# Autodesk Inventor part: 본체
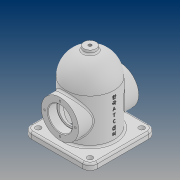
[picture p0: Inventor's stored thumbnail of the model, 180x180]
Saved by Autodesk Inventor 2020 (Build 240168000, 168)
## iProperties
Created: 2021-08
Part Number: 본체
Material: 일반
Document SubType Name: Modeling
Designer: PC312-
Density: 1 g/cm^3
Appearance: 기본값
Author: PC312-
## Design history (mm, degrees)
sketch "스케치1"
  geometry: C1 r 40 at (0, 0); 1 further point
  constraints: 1 centre point, 1 coincident
  dimensions: "d0" = 80 diameter of C1
extrude "돌출1" new body sketch "스케치1" distance "d1" = 36; taper "d3" = 0 deg; dims "d2" = 48, "d4" = 0
sketch "스케치2"
  geometry: C1 r 40 at (0, 0); 1 further point
  constraints: 1 centre point, 1 coincident
  dimensions: "d6" = 80 diameter of C1
extrude "돌출2" join sketch "스케치2" distance "d7" = 40; taper "d8" = 0 deg
fillet "모깎기2" dims "d9" = 40
sketch "스케치4"
  geometry: 1 further point
feature "쉘1" dims "d10" = 8
node "작업 평면1"
sketch "스케치5"
  geometry: L1 (-40, -48)-(40, -48) reference; C1 r 31 at (0, 0); 1 further point
  constraints: 1 centre point, 1 coincident
  dimensions: "d29" = 48 distance from line of L1 C1.centre; "d30" = 62 diameter of C1
extrude "돌출5" join sketch "스케치5" stored distance "d31" = 10; taper "d32" = 0 deg
sketch "스케치6"
  geometry: L1 (20, 50)-(20, 35); L2 (20, 35)-(16.5, 35); L3 (16.5, 35)-(16.5, -35); L4 (16.5, -35)-(20, -35); L5 (20, -35)-(20, -50); L6 (0, 71.621)-(0, -88.049); L7 (-48, -32)-(-48, 32) reference; L8 (20, 50)-(0, 50); L9 (20, -50)-(0, -50); L10 (31, 50)-(-31, 50) reference; L11 (31, -50)-(-31, -50) reference; 2 further points
  constraints: 16 end point, 4 horizontal, 4 point on line, 3 vertical, 2 collinear, 1 coincident
  dimensions: "d33" = 48 distance between parallel lines of L7 L6; "d34" = 15 distance between parallel lines of L2 L8; "d35" = 15 distance between parallel lines of L9 L4; "d36" = 40 diameter of L5 L6; "d37" = 33 diameter of L3 L6
revolve "회전3" sketch "스케치6" stored, may be unused: angle "d38" = 90 deg
sketch "스케치7"
  geometry: L1 (55, 55)-(-55, 55); L2 (-55, 55)-(-55, -55); L3 (-55, -55)-(55, -55); L4 (55, -55)-(55, 55); L5 (55, 55)-(-55, -55); L6 (-55, 55)-(55, -55); C1 r 32 at (0, 0) reference; 1 further point
  constraints: 12 end point, 2 midpoint, 2 parallel, 1 horizontal, 1 perpendicular
  dimensions: "d24" = 110 distance between parallel lines of L3 L1; "d25" = 110 distance between parallel lines of L2 L4
extrude "돌출4" join sketch "스케치7" distance "d26" = 10; taper "d27" = 0 deg
fillet "모깎기4" dims "d39" = 0.3
node "작업 평면2"
sketch "스케치8"
  geometry: C1 r 10 at (0, 0); 1 further point
  constraints: 1 centre point, 1 coincident
  dimensions: "d41" = 20 diameter of C1
extrude "돌출6" join sketch "스케치8" stored distance "d42" = 10; taper "d43" = 0 deg
sketch "스케치9"
  geometry: C1 r 10 at (0, 0) reference; 2 further points
  constraints: 1 coincident
hole "구멍1" sketch "스케치9" at (0, 0) diameter "d44" = 5.1881; stored, may be unused: countersink angle "d48" = 90 deg, drill point angle "d50" = 118 deg; dims "d45" = 18, "d46" = 4, "d47" = 2, "d49" = 16
sketch "스케치10"
  geometry: 2 further points
  constraints: 1 vertical alignment
  dimensions: "d51" = 25.5 distance of point (0, 0) point (0, 25.5)
hole "구멍2" sketch "스케치10" at (0, 25.5) diameter "d52" = 3.242; stored, may be unused: countersink angle "d56" = 90 deg, drill point angle "d58" = 118 deg; dims "d53" = 8, "d54" = 4, "d55" = 2, "d57" = 10
fillet "모깎기5" dims "d62" = 12
sketch "스케치11"
  geometry: C1 r 4.5 at (43, 43); C2 r 4.5 at (43, -43); C3 r 4.5 at (-43, -43); C4 r 4.5 at (-43, 43); A1 r 12 centre (43, 43) between (55, 43) and (43, 55) reference; A2 r 12 centre (43, -43) between (43, -55) and (55, -43) reference; A3 r 12 centre (-43, -43) between (-55, -43) and (-43, -55) reference; A4 r 12 centre (-43, 43) between (-43, 55) and (-55, 43) reference; 1 further point
  constraints: 4 centre point, 4 concentric
  dimensions: "d63" = 9 diameter of C1; "d64" = 9 diameter of C2; "d65" = 9 diameter of C3; "d66" = 9 diameter of C4
extrude "돌출7" cut sketch "스케치11" extent not by distance; stored distance "d67" = 0; taper "d68" = 0 deg
node "작업 평면3"
sketch "스케치12"
  geometry: L1 (-48, -43)-(-48, 43) reference; 2 further points
  constraints: 1 other
  dimensions: "d71" = 48 distance from line of L1 point (0, 0); "d72" = 0 distance of point (0, 0) point (0, 0)
feature "엠보싱1" sketch "스케치12" dims "d33" = 48, "d34" = 15, "d35" = 15, "d36" = 40, "d37" = 33, "d73" = 0.5, "d74" = 0
fillet "모깎기6" dims "d75" = 3
fillet "모깎기7" dims "d76" = 3
chamfer "모따기1" distance "d77" = 1; stored, may be unused: second distance "d78" = 2, angle "d79" = 45 deg
node "솔리드1"
mirror "미러1"
pattern_circular "원형 패턴1" dims angle "d60" = 360 deg
mirror "미러2"
feature "A9D066F2-1C7D-4E18-AEED-F7BC21143FA4" dims "d44" = 5.1881, "d45" = 18, "d46" = 4, "d47" = 2, "d48" = 90 deg, "d49" = 16, "d50" = 118 deg
other parameters: "d40" = -129, "d69" = 44.75
